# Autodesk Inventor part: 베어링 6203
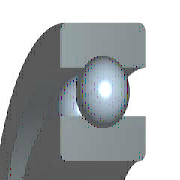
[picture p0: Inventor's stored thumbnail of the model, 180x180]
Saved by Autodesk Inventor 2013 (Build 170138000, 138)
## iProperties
Created: 2012-02
Part Number: 베어링 6203
Material: 강철, 연강
Description: 깊은 그루브 볼 베어링
Document SubType Name: Modeling
Standard: KS B 2023
Designer: mduedu
Standards Organization: KS
Language: ko-KR
Size Designation: 6203 - 17 x 40 x 12
Categories: <MemberInstance><Categories><Category DisplayName="샤프트 부품" InternalName="7f7aeb1f-a693-4053-b835-cee3144e0d98" Mnemonic="SHFT"><Category DisplayName="베어링" Inter
Density: 7.86 g/cm^3
Mass: 64.9809 g
Surface Area: 64.3582 cm^2
Volume: 8.26729 cm^3
IsCustomPart: 1
Author: mduedu
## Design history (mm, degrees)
sketch "스케치" dims "d0" = 5.98 (= -0.26 x WD + 0.26 x BD)
  geometry: L1 (3.01, 14.25)-(8.99, 14.25); L2 (6, 14.25)-(6, 11.26); L3 (6, 14.25)-(6, 17.24); L4 (3.778, 12.249)-(0, 12.249); L5 (0, 8.5)-(12, 8.5); L6 (3.778, 16.251)-(0, 16.251); L7 (0, 20)-(12, 20); L8 (12, 8.5)-(12, 12.249); L9 (8.222, 12.249)-(12, 12.249); L10 (8.222, 16.251)-(12, 16.251); L11 (12, 20)-(12, 16.251); L12 (-1.4, 0)-(8.4, 0) reference; L13 (0, -0.3)-(0, 5.3) reference
  constraints: 22 end point, 4 point on line, 2 collinear, 2 perpendicular, 2 symmetric about line, 1 midpoint, 1 parallel, 14 other
  dimensions: "d9" = 17 diameter of L5 L12 (= WD); "d11" = 40 diameter of L7 L12 (= BD); "d12" = 12 distance between parallel lines of L8 L13 (= KB); "d13" = 24.498 diameter of L9 L12 (= 0.326 x BD + 0.674 x WD)
revolve "본체" stored, may be unused: angle "d6" = 90 deg
revolve "볼" stored, may be unused: angle "d7" = 90 deg
pattern_circular "IDS_ARRAYBALL[SIMPL:T]" dims angle "d3" = 360 deg
body "Solid1"
fillet "모깎기1" dims "d1" = 0.6 (= KRS)
other parameters: "WD" = 17 [user parameter; used in 5 equation terms], "BD" = 40 [user parameter; used in 5 equation terms], "KB" = 12 [user parameter; used in 1 equation term], "KRS" = 0.6 [user parameter; used in 1 equation term], "d4" = 0, "d5" = 0, "d8" = 0, "d14" = 0, "d15" = 0, "BBA" = 0 [user parameter], "BC0" = 4750000 [user parameter], "BC" = 9560000 [user parameter], "WR" = 8.5 (= 0.5 x WD) [user parameter]
